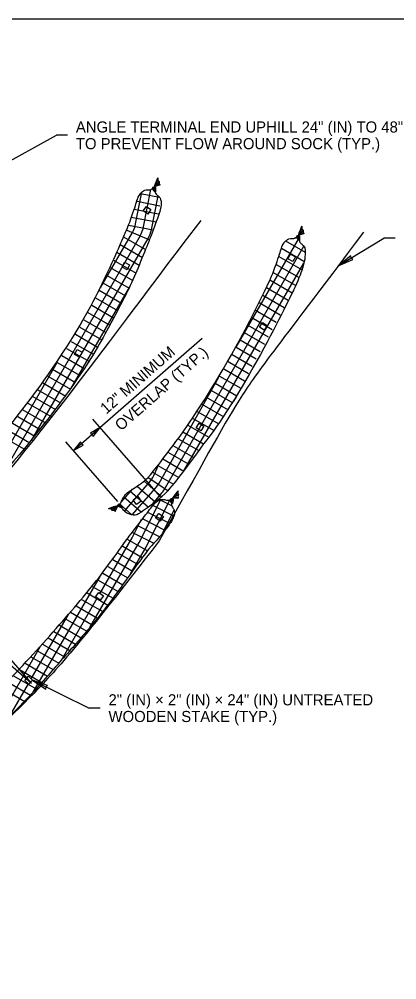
# Model space of a CAD drawing. Extents: x 99862 to 103680, y 99470 to 102076.
# Drawn here: x 100941 to 101484, y 100693 to 102076 of the extents above; entities that cross this region are included whole.
import ezdxf

# ---------------------------------------------------------------- set-up
doc = ezdxf.new("R2010")
doc.units = 0
for name, color, linetype in [('Level 1', 7, 'Continuous'), ('Level 15', 7, 'Continuous'), ('Level 20', 7, 'Continuous'), ('Level 3', 7, 'Continuous'), ('Level 4', 7, 'Continuous'), ('Level 8', 7, 'Continuous'), ('Level 9', 7, 'Continuous')]:
    doc.layers.add(name, color=color, linetype=linetype)

msp = doc.modelspace()

# ---------------------------------------------------------------- linework, layer by layer
at = {"layer": 'Level 1'}
msp.add_lwpolyline([(99862, 99999.5), (103151, 99999.5), (103151, 102075.5), (99862, 102075.5)], close=True, dxfattribs=at)
at = {"layer": 'Level 15'}
for p, q in [((100848.6, 101828.3), (100994.7, 101908.4)), ((101010.7, 101908.4), (100994.7, 101908.4)), ((101399.9, 101720.6), (101465.7, 101760.3)), ((101481.7, 101760.3), (101465.7, 101760.3)), ((101019.4, 101454.5), (101204.1, 101616.4)), ((101144.4, 101388.1), (101046.9, 101499.8)), ((100959, 101119.8), (100881.2, 101208.9)), ((100881.8, 101186.5), (100959, 101119.8)), ((100960.4, 101124.3), (101041.6, 101083.9)), ((101057.6, 101083.9), (101041.6, 101083.9))]:
    msp.add_line(p, q, dxfattribs=at)
for points in [[(101399.9, 101720.6), (101421, 101729.8), (101418.5, 101731.8), (101417.9, 101734.9)], [(101057.4, 101487.8), (101043.5, 101479.8), (101046.1, 101477.9), (101047.6, 101475.1)], [(101019.4, 101454.5), (101033.2, 101462.5), (101030.7, 101464.3), (101029.2, 101467.1)], [(100960.4, 101124.3), (100979.5, 101111.4), (100979.8, 101114.5), (100982.1, 101116.7)]]:
    msp.add_lwpolyline(points, close=True, dxfattribs=at)
msp.add_lwpolyline([(101083, 101381.5), (101008.4, 101467)], dxfattribs=at)
at = {"layer": 'Level 3'}
for points in [[(101119.5, 101799.6), (101124, 101806.1), (101130.6, 101801.5), (101126, 101795)], [(101327.5, 101730.4), (101331.3, 101737.5), (101338.4, 101733.7), (101334.6, 101726.6)], [(101089.1, 101718.5), (101092.8, 101725.6), (101099.9, 101721.8), (101096.2, 101714.8)], [(101286.8, 101632.3), (101291.1, 101639), (101297.8, 101634.7), (101293.5, 101628)], [(101020.9, 101593), (101024.6, 101600.1), (101031.7, 101596.4), (101028, 101589.3)], [(101195.8, 101487.2), (101200.1, 101493.9), (101206.9, 101489.6), (101202.5, 101482.8)], [(101105.2, 101383.6), (101111.7, 101388.3), (101116.4, 101381.8), (101109.9, 101377.1)], [(101137.3, 101357.6), (101141.9, 101364.2), (101148.5, 101359.7), (101143.9, 101353.1)], [(101051, 101244.1), (101055.9, 101250.5), (101062.3, 101245.6), (101057.4, 101239.3)], [(100949.1, 101123.9), (100954.5, 101129.7), (100960.4, 101124.3), (100954.9, 101118.4)]]:
    msp.add_lwpolyline(points, close=True, dxfattribs=at)
at = {"layer": 'Level 4'}
for p, q in [((101120, 101776.8), (101130.4, 101830.4)), ((101130.4, 101830.4), (101130.4, 101830.4)), ((101108.6, 101781), (101117.5, 101826.7)), ((101115.6, 101824.8), (101142.9, 101819.5)), ((101131.4, 101772.5), (101140.8, 101821.2)), ((101106.5, 101802.1), (101141.5, 101795.3)), ((101110.7, 101813.5), (101143.6, 101807.1)), ((101102.2, 101790.7), (101137.9, 101783.8)), ((101098.2, 101779.2), (101133.9, 101772.3)), ((100912.9, 101413.7), (101115.4, 101764.4)), ((100958.7, 101468.9), (101126.8, 101760.1)), ((101058.5, 101689.8), (101104, 101768.6)), ((101091.1, 101762.2), (101122.8, 101743.9)), ((101095.9, 101772), (101127.7, 101758.2)), ((101253.1, 101603.4), (101344.3, 101761.3)), ((101086.5, 101751.1), (101118.4, 101732.6)), ((101149.4, 101398.1), (101350.7, 101748.8)), ((101318.2, 101745.9), (101350.5, 101727.3)), ((101324.3, 101756.3), (101352.4, 101740)), ((101081.7, 101740), (101113.9, 101721.4)), ((101314.6, 101734.2), (101348, 101714.9)), ((101071.8, 101717.9), (101104.4, 101699.2)), ((101076.8, 101728.9), (101109.2, 101710.2)), ((101178.1, 101425.4), (101350.7, 101724.4)), ((101310.8, 101722.5), (101343.6, 101703.5)), ((101066.7, 101707), (101099.3, 101688.2)), ((101306.6, 101711), (101339, 101692.4)), ((101015.5, 101543.4), (101100.3, 101690.2)), ((101061.6, 101696.2), (101094, 101677.4)), ((101301.8, 101700.2), (101333.6, 101681.8)), ((101056.3, 101685.3), (101088.3, 101666.9)), ((101291.4, 101678.4), (101322.2, 101660.7)), ((101296.6, 101689.3), (101327.9, 101671.2)), ((101045.4, 101663.9), (101076.9, 101645.8)), ((101050.9, 101674.6), (101082.5, 101656.3)), ((101286.2, 101667.6), (101316.5, 101650.1)), ((101039.8, 101653.3), (101071.3, 101635.1)), ((101280.9, 101656.8), (101310.8, 101639.5)), ((101034.1, 101642.7), (101065.7, 101624.5)), ((101270.1, 101635.3), (101299.4, 101618.4)), ((101275.5, 101646), (101305.1, 101629)), ((101022.1, 101622), (101054.6, 101603.2)), ((101028.2, 101632.3), (101060.2, 101613.8)), ((101264.5, 101624.7), (101293.7, 101607.9)), ((101015.8, 101611.7), (101048.6, 101592.8)), ((101258.9, 101614.1), (101287.9, 101597.3)), ((101009.3, 101601.6), (101042.3, 101582.6)), ((101247.4, 101593), (101276.4, 101576.3)), ((101253.2, 101603.5), (101282.1, 101586.8)), ((100874.4, 101370.9), (100995.9, 101581.3)), ((100996, 101581.6), (101029, 101562.5)), ((101002.7, 101591.6), (101035.7, 101572.5)), ((101241.5, 101582.6), (101270.7, 101565.7)), ((100989.2, 101571.7), (101022.1, 101552.7)), ((101235.4, 101572.2), (101265.2, 101555)), ((100975.3, 101552), (101008, 101533.1)), ((100982.3, 101561.8), (101015.1, 101542.8)), ((101142.3, 101407.7), (101228.4, 101560.5)), ((101223, 101551.7), (101254.3, 101533.6)), ((101229.2, 101561.9), (101259.7, 101544.3)), ((100968.2, 101542.2), (101000.8, 101523.4)), ((101216.6, 101541.5), (101248.3, 101523.2)), ((100961, 101532.5), (100993.5, 101513.7)), ((101210.2, 101531.3), (101241.8, 101513.1)), ((101249.7, 101525.5), (101253.5, 101532)), ((100946.5, 101513.2), (100978.8, 101494.5)), ((100953.8, 101522.8), (100986.2, 101504.1)), ((101197.3, 101511.1), (101228.3, 101493.2)), ((101203.8, 101521.2), (101235.2, 101503.1)), ((100939.1, 101503.6), (100971.4, 101485)), ((101190.7, 101501), (101221.3, 101483.4)), ((100924.2, 101484.5), (100956.3, 101466)), ((100931.7, 101494), (100963.8, 101475.4)), ((101183.8, 101491.1), (101214, 101473.7)), ((100916.6, 101475), (100948.7, 101456.5)), ((101169.6, 101471.6), (101199.3, 101454.5)), ((101176.6, 101481.5), (101206.3, 101464.3)), ((101162.3, 101462), (101192.3, 101444.7)), ((101147.9, 101442.6), (101178, 101425.2)), ((101155.1, 101452.3), (101185.2, 101434.9)), ((101134.6, 101418.6), (101141.8, 101434.5)), ((101140.6, 101433), (101170.5, 101415.7)), ((101126.6, 101415.9), (101154.9, 101397)), ((101133, 101423.5), (101162.9, 101406.2)), ((101092.5, 101367.5), (101128.3, 101408.7)), ((101103.6, 101362), (101137.6, 101401.1)), ((101110.6, 101403.4), (101137, 101380.3)), ((101120.8, 101410.4), (101146.8, 101387.7)), ((101087.7, 101380.4), (101104, 101399)), ((101091.6, 101388), (101116.9, 101366)), ((101100.2, 101396.5), (101127.1, 101373.1)), ((101132.5, 101377), (101145.4, 101392.4)), ((101085.5, 101377.5), (101086.2, 101376.8)), ((101089.6, 101373.9), (101103.2, 101362.1)), ((101113.5, 101322.1), (101145.5, 101385)), ((101123.6, 101315.9), (101158.5, 101384.1)), ((101132.6, 101376.7), (101132.8, 101376.5)), ((101132.9, 101375.9), (101163.8, 101360.3)), ((101142.9, 101384.3), (101160.4, 101375.4)), ((101125.6, 101366.2), (101158.2, 101349.6)), ((101147.9, 101336.9), (101164.2, 101368.8)), ((101103.4, 101328.8), (101117.1, 101355.7)), ((101110.2, 101347.1), (101142.3, 101330.8)), ((101117.9, 101356.7), (101150.7, 101340)), ((101103.2, 101337.2), (101133.9, 101321.6)), ((101042.9, 101200), (101113.6, 101322.2)), ((101057.5, 101249.3), (101103.5, 101328.8)), ((101089.3, 101317.5), (101118.2, 101300.9)), ((101096.3, 101327.3), (101125.5, 101310.5)), ((101082.5, 101307.6), (101111.1, 101291.1)), ((101101.2, 101277.1), (101123.6, 101315.8)), ((101075.6, 101297.7), (101104.1, 101281.2)), ((101061.3, 101278.3), (101090.3, 101261.5)), ((101068.5, 101287.9), (101097.3, 101271.4)), ((100961.4, 101106.9), (101057.6, 101273.4)), ((101053.9, 101268.7), (101083.3, 101251.7)), ((101038.7, 101249.8), (101068.8, 101232.3)), ((101046.3, 101259.2), (101076.1, 101242)), ((101001.9, 101152.9), (101053.5, 101242.3)), ((101030.8, 101240.4), (101061.4, 101222.8)), ((101014.9, 101221.9), (101046.1, 101203.9)), ((101022.9, 101231.1), (101053.8, 101213.3)), ((100958.6, 101126), (101012, 101218.5)), ((101006.9, 101212.7), (101038.3, 101194.5)), ((100990.8, 101194.3), (101022.3, 101176.1)), ((100998.9, 101203.5), (101030.4, 101185.3)), ((100982.6, 101185.1), (101014.2, 101166.9)), ((100898.4, 101045.7), (100972, 101173.2)), ((100966.3, 101166.8), (100998, 101148.5)), ((100974.5, 101176), (101006.1, 101157.7)), ((100958.1, 101157.7), (100989.9, 101139.3)), ((100941.5, 101139.6), (100973.8, 101120.9)), ((100949.8, 101148.7), (100981.9, 101130.1)), ((100933, 101130.6), (100965.8, 101111.7)), ((100915.8, 101112.9), (100949.2, 101093.6)), ((100924.5, 101121.7), (100957.5, 101102.6)), ((100927.2, 101071.7), (100954.5, 101118.8))]:
    msp.add_line(p, q, dxfattribs=at)
for centre, start, end in [((101069.3, 101788.6), 330, 349.042), ((101080.7, 101784.4), 330, 349.042), ((101092.1, 101780.1), 330, 349.042), ((101098.1, 101435), 318.9635, 335.7978), ((101107.4, 101427.4), 318.9635, 330.5956), ((101114.7, 101418), 320.0311, 330.137)]:
    msp.add_arc(centre, 40, start, end, dxfattribs=at)
at = {"layer": 'Level 8'}
msp.add_open_spline([(101436.3, 101768.9), (101305.1, 101594.6), (101260.5, 101540.5), (101204, 101433.4), (101142.5, 101324.8)], degree=3, dxfattribs=at)
at = {"layer": 'Level 9'}
for p, q in [((101140.3, 101843.9), (101135.3, 101833.9)), ((101142.3, 101842.1), (101135.5, 101834)), ((101347.5, 101774), (101342.5, 101764)), ((101337.6, 101760.4), (101337.6, 101760.5)), ((101349.5, 101772.1), (101342.6, 101764.1)), ((101168.9, 101393.5), (101161.4, 101385.3)), ((101170.3, 101391.2), (101161.5, 101385.4)), ((101072.8, 101371), (101083.2, 101375.3)), ((101074.5, 101368.9), (101083.1, 101375.1))]:
    msp.add_line(p, q, dxfattribs=at)
for points in [[(101140.3, 101847.3), (101140.3, 101843.9), (101142.3, 101842.1), (101142.3, 101838), (101144, 101837.2), (101135.3, 101834)], [(101347.5, 101777.4), (101347.5, 101774), (101349.5, 101772.1), (101349.4, 101768.1), (101351.1, 101767.3), (101342.5, 101764.1)], [(101169.9, 101396.9), (101168.9, 101393.5), (101170.3, 101391.2), (101169.2, 101387.4), (101170.6, 101386.1), (101161.4, 101385.5)], [(101069.4, 101371.3), (101072.8, 101371), (101074.5, 101368.9), (101078.5, 101368.6), (101079.2, 101366.9), (101083.1, 101375.2)]]:
    msp.add_lwpolyline(points, dxfattribs=at)
for points, degree in [([(101140.3, 101847.3), (101134.2, 101834.2), (101137.1, 101831.3), (101137.5, 101826), (101133.2, 101830.2), (101133.4, 101832.3)], 2), ([(101093.9, 101768.8), (101097.6, 101775.8), (101108, 101805.6), (101112.1, 101820.6), (101117.7, 101827.3), (101122, 101829.6), (101126, 101830.2), (101129, 101829.6), (101130.6, 101830.5), (101130.2, 101830.2), (101132.1, 101831.5)], 3), ([(101132.1, 101831.5), (101133.4, 101832.3), (101133.9, 101832.8), (101135.4, 101834.2), (101136.9, 101834), (101137.3, 101832.4), (101136.9, 101828), (101136.7, 101826.2), (101137.6, 101823.7), (101142.4, 101820), (101144.1, 101818.1), (101145.1, 101814.2), (101145.6, 101813.6), (101145.3, 101804.2), (101139.4, 101786.3), (101130.9, 101764.4)], 3), ([(101133.4, 101832.3), (101133.6, 101834.4), (101135, 101833.6), (101137.5, 101827.1), (101134.8, 101829), (101133.7, 101834.1), (101142.3, 101838)], 2), ([(101202.5, 101785.8), (101114, 101672), (101039.8, 101564.6), (100900, 101393.5)], 3), ([(101347.5, 101777.4), (101341.4, 101764.3), (101344.3, 101761.4), (101344.6, 101756.1), (101340.4, 101760.3), (101340.6, 101762.3)], 2), ([(100773.6, 101323.7), (100781.4, 101330.9), (100796.5, 101342.8), (100895.3, 101445.3), (101010, 101597.3), (101066.6, 101703.4), (101091.8, 101763.7), (101093.9, 101768.8)], 3), ([(101130.9, 101764.4), (101125.8, 101751.6), (101102.9, 101693.1), (101078.1, 101648.6), (101038.3, 101571.1), (100920, 101418.7), (100833.9, 101328.5), (100806.3, 101307.4)], 3), ([(101301, 101698.9), (101304.8, 101705.9), (101315.2, 101735.6), (101319.2, 101750.6), (101324.8, 101757.4), (101329.2, 101759.6), (101333.2, 101760.2), (101336.1, 101759.7), (101337.8, 101760.6), (101337.3, 101760.3), (101339.3, 101761.6)], 3), ([(101339.3, 101761.6), (101340.6, 101762.4), (101341.1, 101762.9), (101342.6, 101764.3), (101344, 101764.1), (101344.4, 101762.5), (101344.1, 101758.1), (101343.9, 101756.3), (101344.8, 101753.8), (101349.6, 101750.1), (101351.3, 101748.2), (101352.2, 101744.2), (101352.7, 101743.7), (101352.5, 101734.2), (101350.1, 101720), (101341.9, 101698.3), (101335.7, 101685.6)], 3), ([(101340.6, 101762.3), (101340.7, 101764.5), (101342.2, 101763.6), (101344.7, 101757.1), (101342, 101759), (101340.8, 101764.2), (101349.4, 101768.1)], 2), ([(101171.1, 101473.6), (101177.1, 101482.3), (101189.4, 101497.1), (101262.7, 101616.3), (101301, 101698.9)], 3), ([(101335.7, 101685.6), (101335.5, 101685.1), (101293.8, 101597.6), (101229, 101491.2), (101206.5, 101464.6)], 3), ([(101126.6, 101415.9), (101127.8, 101417.3), (101140.4, 101432.3), (101158.7, 101457.2), (101171.1, 101473.6)], 3), ([(101206.5, 101464.6), (101200.3, 101455.9), (101174.7, 101419.8), (101154.4, 101396.4), (101151.2, 101392.7)], 3), ([(101151.2, 101392.7), (101137.4, 101380.4), (101116, 101365.2), (101108.6, 101360.5), (101096.6, 101363.5), (101090.4, 101369.4), (101088.8, 101372.8), (101085.3, 101373.8), (101082.8, 101374.2), (101082, 101374.8), (101082.8, 101375.9), (101086.6, 101378), (101089.1, 101383.2), (101092.2, 101389.2), (101095.5, 101393.5), (101104.7, 101399.5), (101120.8, 101410), (101126.6, 101415.9)], 3), ([(101169.9, 101396.9), (101160.4, 101385.9), (101162.4, 101382.3), (101161.3, 101377.1), (101158.3, 101382.4), (101159.1, 101384.3)], 2), ([(101159.1, 101384.3), (101159.8, 101386.3), (101161, 101385.1), (101161.6, 101378.2), (101159.5, 101380.7), (101159.8, 101386), (101169.2, 101387.4)], 2), ([(101069.4, 101371.3), (101083, 101376.4), (101085.6, 101373.2), (101090.9, 101372.5), (101087, 101377.1), (101085, 101377)], 2), ([(101085, 101377), (101082.8, 101377), (101083.6, 101375.5), (101089.8, 101372.5), (101088.2, 101375.3), (101083.1, 101376.9), (101077.6, 101368.5)], 2), ([(101099.2, 101331.2), (101112.5, 101348.4), (101126.6, 101366.9), (101137.9, 101381.6), (101143.4, 101383.9), (101148.1, 101384.5), (101152.1, 101383.7), (101154, 101383.1), (101155.9, 101383.4), (101155.4, 101383.3), (101157.6, 101383.9)], 3), ([(101157.6, 101383.9), (101159.1, 101384.3), (101159.8, 101384.6), (101161.6, 101385.4), (101162.9, 101384.8), (101162.8, 101383.1), (101161, 101379.1), (101160.3, 101377.4), (101160.3, 101374.8), (101163.7, 101369.7), (101164.8, 101367.4), (101164.4, 101363.3), (101164.7, 101362.7), (101161.4, 101353.8), (101150.1, 101338.7), (101138.5, 101324.9), (101127.8, 101313.2)], 3), ([(100508, 100847.6), (100517.7, 100851.8), (100535.9, 100857.9), (100663.5, 100921.2), (100822.6, 101025.8), (100911.6, 101106.7), (100992, 101195.1), (101059, 101273.3), (101091.4, 101320.8), (101099.2, 101331.2)], 3), ([(101142.5, 101324.8), (101030.4, 101179.2), (100966.3, 101105.9), (100844.5, 100991.2), (100709.3, 100905.3), (100580.5, 100837.5), (100320.2, 100738.9), (100199.3, 100698.3), (100142.4, 100673.8)], 3), ([(101127.8, 101313.2), (101117.8, 101300.9), (101077.8, 101243.2), (101038.6, 101194.3), (101003.5, 101155), (100942.3, 101084.8), (100904, 101051.2), (100840.4, 100991.6), (100677.8, 100887.9), (100566.4, 100831.8), (100533.3, 100821.2)], 3)]:
    msp.add_open_spline(points, degree=degree, dxfattribs=at)

# ---------------------------------------------------------------- texts
at = {"layer": 'Level 20'}
for s, p in [('ANGLE TERMINAL END UPHILL 24" (IN) TO 48" (IN) ', (101022.7, 101912.4)), ('TO PREVENT FLOW AROUND SOCK (TYP.)', (101022.7, 101888.4)), ('2" (IN) × 2" (IN) × 24" (IN) UNTREATED ', (101069.6, 101087.9)), ('WOODEN STAKE (TYP.)', (101069.6, 101063.9))]:
    msp.add_text(s, height=16, dxfattribs=at).set_placement(p)
for s, p in [('12" MINIMUM ', (101066.4, 101506.3)), ('OVERLAP (TYP.)', (101087.5, 101482.2))]:
    msp.add_text(s, height=16, rotation=41.2336, dxfattribs=at).set_placement(p)

doc.saveas('drawing.dxf')
